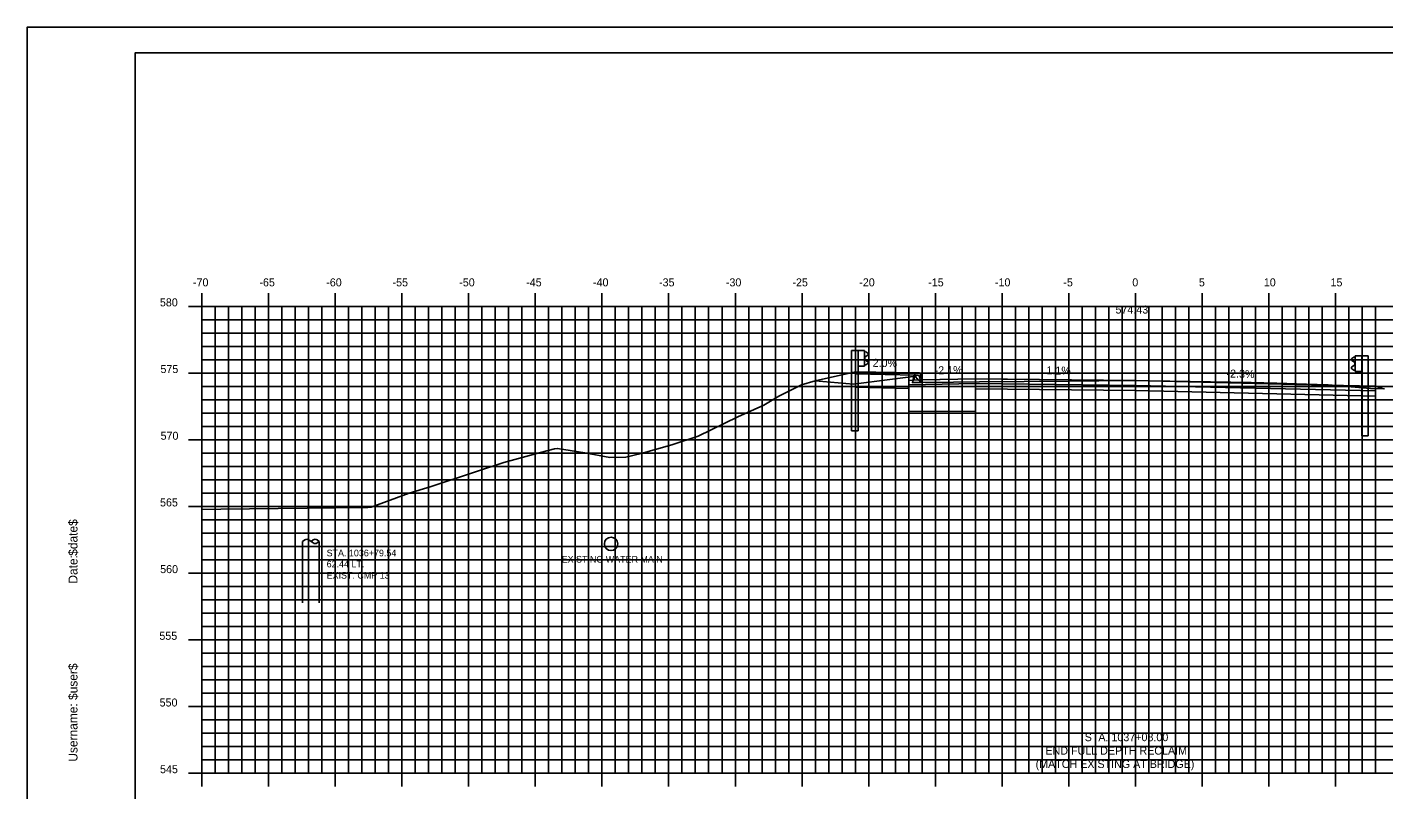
# Model space of a CAD drawing. Extents: x 1060559 to 1060729, y 779716 to 779826.
# Drawn here: x 1060559 to 1060660.7, y 779768.5 to 779825.6 of the extents above; entities that cross this region are included whole.
import ezdxf

# ---------------------------------------------------------------- set-up
doc = ezdxf.new("R2010")
doc.units = 0
for name, color, linetype in [('ANNOTATION', 7, 'Continuous'), ('BORDER', 7, 'Continuous'), ('D_Roadway_Berm', 7, 'Continuous'), ('D_Roadway_Centerline', 7, 'Continuous'), ('D_Roadway_Centerline_Text', 7, 'Continuous'), ('D_Roadway_Edge_Pavement', 7, 'Continuous'), ('D_Roadway_Edge_Shoulder', 7, 'Continuous'), ('D_Roadway_Pavement', 7, 'Continuous'), ('D_Roadway_Sidewalks_Paved', 7, 'Continuous'), ('D_Roadway_SubGrade', 7, 'Continuous'), ('D_Text_Monospaced', 7, 'Continuous'), ('Existing Water Main', 7, 'Continuous'), ('H_V ANNOTATION', 7, 'Continuous'), ('M_Guardrail', 7, 'Continuous'), ('MAJOR', 7, 'Continuous'), ('MINOR', 7, 'Continuous'), ('PLOT BOUNDARY', 7, 'Continuous'), ('S_Curb_Type_3', 7, 'Continuous'), ('S_Guardrail_Beam', 7, 'Continuous'), ('S_Roadway_Centerline', 7, 'Continuous'), ('S_Roadway_Edge_Pavement', 7, 'Continuous'), ('S_Utilities_Pole_Joint', 7, 'Continuous'), ('S_Utilities_Pole_Power', 7, 'Continuous')]:
    doc.layers.add(name, color=color, linetype=linetype)

msp = doc.modelspace()

# ---------------------------------------------------------------- linework, layer by layer
at = {"layer": 'ANNOTATION'}
msp.add_line((1060621.08, 779799.81), (1060618.06, 779799.13), dxfattribs=at)
at = {"layer": 'BORDER'}
msp.add_lwpolyline([(1060567.08, 779718.71), (1060727.08, 779718.71), (1060727.08, 779823.71), (1060567.08, 779823.71)], close=True, dxfattribs=at)
at = {"layer": 'D_Roadway_Berm'}
msp.add_lwpolyline([(1060626.08, 779799.19), (1060626.08, 779799.19)], dxfattribs=at)
at = {"layer": 'D_Roadway_Centerline'}
for points in [[(1060621.08, 779799.81), (1060625.66, 779799.72), (1060625.83, 779799.73), (1060625.89, 779799.72), (1060625.93, 779799.68), (1060625.96, 779799.63), (1060626.08, 779799.19)], [(1060625.82, 779799.17), (1060626.07, 779799.19), (1060626.08, 779799.19), (1060626.08, 779799.19), (1060630.08, 779799.27), (1060642.08, 779799.14), (1060654.08, 779798.86), (1060660.08, 779798.73), (1060660.66, 779798.53)]]:
    msp.add_lwpolyline(points, dxfattribs=at)
at = {"layer": 'D_Roadway_Edge_Pavement'}
msp.add_lwpolyline([(1060630.08, 779799.27), (1060630.08, 779799.27), (1060642.08, 779799.14), (1060654.08, 779798.86), (1060642.08, 779799.14), (1060642.08, 779799.14)], close=True, dxfattribs=at)
at = {"layer": 'D_Roadway_Edge_Shoulder'}
msp.add_line((1060654.08, 779798.86), (1060660.08, 779798.73), dxfattribs=at)
msp.add_lwpolyline([(1060625.46, 779799.17), (1060626.08, 779799.19), (1060630.08, 779799.27), (1060630.08, 779798.92), (1060625.08, 779798.82)], dxfattribs=at)
msp.add_lwpolyline([(1060630.08, 779799.27), (1060626.08, 779799.19), (1060630.08, 779799.27)], close=True, dxfattribs=at)
at = {"layer": 'D_Roadway_Pavement'}
for p, q in [((1060626.08, 779799.19), (1060630.08, 779799.27)), ((1060630.08, 779799.27), (1060630.08, 779796.86))]:
    msp.add_line(p, q, dxfattribs=at)
msp.add_lwpolyline([(1060630.08, 779796.86), (1060625.08, 779796.84), (1060625.08, 779798.82)], dxfattribs=at)
msp.add_lwpolyline([(1060630.08, 779799.27), (1060630.08, 779799.27), (1060642.08, 779799.14), (1060642.08, 779799.14)], close=True, dxfattribs=at)
at = {"layer": 'D_Roadway_Sidewalks_Paved'}
msp.add_lwpolyline([(1060625.66, 779799.72), (1060621.08, 779799.81), (1060621.08, 779799.64), (1060625.53, 779799.55), (1060625.54, 779799.62), (1060625.56, 779799.67), (1060625.6, 779799.7)], close=True, dxfattribs=at)
msp.add_lwpolyline([(1060626.07, 779799.19), (1060626.08, 779799.19), (1060626.08, 779799.19), (1060626.07, 779799.02), (1060626.07, 779799.02), (1060626.07, 779799.19)], dxfattribs=at)
at = {"layer": 'D_Roadway_SubGrade'}
for points in [[(1060625.53, 779799.55), (1060621.08, 779799.64), (1060621.08, 779798.64), (1060625.07, 779798.56), (1060625.08, 779798.82), (1060625.08, 779799.15), (1060625.46, 779799.17)], [(1060630.08, 779799.27), (1060630.08, 779799.27), (1060626.1, 779799.19), (1060626.07, 779799.19), (1060626.07, 779799.19), (1060626.08, 779799.19), (1060626.08, 779799.19), (1060630.08, 779799.27), (1060634.08, 779799.23), (1060634.08, 779799.23)]]:
    msp.add_lwpolyline(points, close=True, dxfattribs=at)
for points in [[(1060626.07, 779799.02), (1060626.08, 779799.19), (1060626.08, 779799.19), (1060626.07, 779799.19), (1060626.07, 779799.02), (1060626.07, 779799.02)], [(1060630.08, 779799.27), (1060630.08, 779798.92), (1060642.08, 779798.78), (1060660.08, 779798.37)], [(1060630.08, 779799.27), (1060630.08, 779798.52), (1060642.08, 779798.39), (1060660.08, 779797.98), (1060660.08, 779798.73)]]:
    msp.add_lwpolyline(points, dxfattribs=at)
at = {"layer": 'Existing Water Main'}
msp.add_circle((1060602.76, 779786.9), 0.501, dxfattribs=at)
at = {"layer": 'M_Guardrail'}
for p, q in [((1060620.79, 779801.39), (1060620.79, 779795.39)), ((1060621.28, 779801.39), (1060620.79, 779801.39)), ((1060659.04, 779801), (1060659.53, 779801)), ((1060659.53, 779801), (1060659.53, 779795)), ((1060621.28, 779795.39), (1060621.28, 779800.22)), ((1060659.04, 779795), (1060659.04, 779799.83)), ((1060621.28, 779795.39), (1060620.79, 779795.39)), ((1060659.04, 779795), (1060659.53, 779795))]:
    msp.add_line(p, q, dxfattribs=at)
at = {"layer": 'MAJOR'}
for p, q in [((1060572.08, 779805.71), (1060572.08, 779804.71)), ((1060577.08, 779805.71), (1060577.08, 779804.71)), ((1060582.08, 779805.71), (1060582.08, 779804.71)), ((1060587.08, 779805.71), (1060587.08, 779804.71)), ((1060592.08, 779805.71), (1060592.08, 779804.71)), ((1060597.08, 779805.71), (1060597.08, 779804.71)), ((1060602.08, 779805.71), (1060602.08, 779804.71)), ((1060607.08, 779805.71), (1060607.08, 779804.71)), ((1060612.08, 779805.71), (1060612.08, 779804.71)), ((1060617.08, 779805.71), (1060617.08, 779804.71)), ((1060622.08, 779805.71), (1060622.08, 779804.71)), ((1060627.08, 779805.71), (1060627.08, 779804.71)), ((1060632.08, 779805.71), (1060632.08, 779804.71)), ((1060637.08, 779805.71), (1060637.08, 779804.71)), ((1060642.08, 779805.71), (1060642.08, 779804.71)), ((1060647.08, 779805.71), (1060647.08, 779804.71)), ((1060652.08, 779805.71), (1060652.08, 779804.71)), ((1060657.08, 779805.71), (1060657.08, 779804.71)), ((1060571.08, 779804.71), (1060572.08, 779804.71)), ((1060572.08, 779804.71), (1060712.08, 779804.71)), ((1060572.08, 779769.71), (1060572.08, 779804.71)), ((1060572.08, 779769.71), (1060572.08, 779804.71)), ((1060572.08, 779804.71), (1060712.08, 779804.71)), ((1060577.08, 779769.71), (1060577.08, 779804.71)), ((1060582.08, 779769.71), (1060582.08, 779804.71)), ((1060587.08, 779769.71), (1060587.08, 779804.71)), ((1060592.08, 779769.71), (1060592.08, 779804.71)), ((1060597.08, 779769.71), (1060597.08, 779804.71)), ((1060602.08, 779769.71), (1060602.08, 779804.71)), ((1060607.08, 779769.71), (1060607.08, 779804.71)), ((1060612.08, 779769.71), (1060612.08, 779804.71)), ((1060617.08, 779769.71), (1060617.08, 779804.71)), ((1060622.08, 779769.71), (1060622.08, 779804.71)), ((1060627.08, 779769.71), (1060627.08, 779804.71)), ((1060632.08, 779769.71), (1060632.08, 779804.71)), ((1060637.08, 779769.71), (1060637.08, 779804.71)), ((1060642.08, 779769.71), (1060642.08, 779804.71)), ((1060647.08, 779769.71), (1060647.08, 779804.71)), ((1060652.08, 779769.71), (1060652.08, 779804.71)), ((1060657.08, 779769.71), (1060657.08, 779804.71)), ((1060571.08, 779799.71), (1060572.08, 779799.71)), ((1060572.08, 779799.71), (1060712.08, 779799.71)), ((1060571.08, 779794.71), (1060572.08, 779794.71)), ((1060572.08, 779794.71), (1060712.08, 779794.71)), ((1060571.08, 779789.71), (1060572.08, 779789.71)), ((1060572.08, 779789.71), (1060712.08, 779789.71)), ((1060571.08, 779784.71), (1060572.08, 779784.71)), ((1060572.08, 779784.71), (1060712.08, 779784.71)), ((1060571.08, 779779.71), (1060572.08, 779779.71)), ((1060572.08, 779779.71), (1060712.08, 779779.71)), ((1060571.08, 779774.71), (1060572.08, 779774.71)), ((1060572.08, 779774.71), (1060712.08, 779774.71)), ((1060571.08, 779769.71), (1060572.08, 779769.71)), ((1060572.08, 779769.71), (1060712.08, 779769.71)), ((1060572.08, 779769.71), (1060712.08, 779769.71)), ((1060572.08, 779768.7), (1060572.08, 779769.71)), ((1060577.08, 779768.7), (1060577.08, 779769.71)), ((1060582.08, 779768.7), (1060582.08, 779769.71)), ((1060587.08, 779768.7), (1060587.08, 779769.71)), ((1060592.08, 779768.7), (1060592.08, 779769.71)), ((1060597.08, 779768.7), (1060597.08, 779769.71)), ((1060602.08, 779768.7), (1060602.08, 779769.71)), ((1060607.08, 779768.7), (1060607.08, 779769.71)), ((1060612.08, 779768.7), (1060612.08, 779769.71)), ((1060617.08, 779768.7), (1060617.08, 779769.71)), ((1060622.08, 779768.7), (1060622.08, 779769.71)), ((1060627.08, 779768.7), (1060627.08, 779769.71)), ((1060632.08, 779768.7), (1060632.08, 779769.71)), ((1060637.08, 779768.7), (1060637.08, 779769.71)), ((1060642.08, 779768.7), (1060642.08, 779769.71)), ((1060647.08, 779768.7), (1060647.08, 779769.71)), ((1060652.08, 779768.7), (1060652.08, 779769.71)), ((1060657.08, 779768.7), (1060657.08, 779769.71))]:
    msp.add_line(p, q, dxfattribs=at)
at = {"layer": 'MINOR'}
for p, q in [((1060573.08, 779769.71), (1060573.08, 779804.71)), ((1060574.08, 779769.71), (1060574.08, 779804.71)), ((1060575.08, 779769.71), (1060575.08, 779804.71)), ((1060576.08, 779769.71), (1060576.08, 779804.71)), ((1060578.08, 779769.71), (1060578.08, 779804.71)), ((1060579.08, 779769.71), (1060579.08, 779804.71)), ((1060580.08, 779769.71), (1060580.08, 779804.71)), ((1060581.08, 779769.71), (1060581.08, 779804.71)), ((1060583.08, 779769.71), (1060583.08, 779804.71)), ((1060584.08, 779769.71), (1060584.08, 779804.71)), ((1060585.08, 779769.71), (1060585.08, 779804.71)), ((1060586.08, 779769.71), (1060586.08, 779804.71)), ((1060588.08, 779769.71), (1060588.08, 779804.71)), ((1060589.08, 779769.71), (1060589.08, 779804.71)), ((1060590.08, 779769.71), (1060590.08, 779804.71)), ((1060591.08, 779769.71), (1060591.08, 779804.71)), ((1060593.08, 779769.71), (1060593.08, 779804.71)), ((1060594.08, 779769.71), (1060594.08, 779804.71)), ((1060595.08, 779769.71), (1060595.08, 779804.71)), ((1060596.08, 779769.71), (1060596.08, 779804.71)), ((1060598.08, 779769.71), (1060598.08, 779804.71)), ((1060599.08, 779769.71), (1060599.08, 779804.71)), ((1060600.08, 779769.71), (1060600.08, 779804.71)), ((1060601.08, 779769.71), (1060601.08, 779804.71)), ((1060603.08, 779769.71), (1060603.08, 779804.71)), ((1060604.08, 779769.71), (1060604.08, 779804.71)), ((1060605.08, 779769.71), (1060605.08, 779804.71)), ((1060606.08, 779769.71), (1060606.08, 779804.71)), ((1060608.08, 779769.71), (1060608.08, 779804.71)), ((1060609.08, 779769.71), (1060609.08, 779804.71)), ((1060610.08, 779769.71), (1060610.08, 779804.71)), ((1060611.08, 779769.71), (1060611.08, 779804.71)), ((1060613.08, 779769.71), (1060613.08, 779804.71)), ((1060614.08, 779769.71), (1060614.08, 779804.71)), ((1060615.08, 779769.71), (1060615.08, 779804.71)), ((1060616.08, 779769.71), (1060616.08, 779804.71)), ((1060618.08, 779769.71), (1060618.08, 779804.71)), ((1060619.08, 779769.71), (1060619.08, 779804.71)), ((1060620.08, 779769.71), (1060620.08, 779804.71)), ((1060621.08, 779769.71), (1060621.08, 779804.71)), ((1060623.08, 779769.71), (1060623.08, 779804.71)), ((1060624.08, 779769.71), (1060624.08, 779804.71)), ((1060625.08, 779769.71), (1060625.08, 779804.71)), ((1060626.08, 779769.71), (1060626.08, 779804.71)), ((1060628.08, 779769.71), (1060628.08, 779804.71)), ((1060629.08, 779769.71), (1060629.08, 779804.71)), ((1060630.08, 779769.71), (1060630.08, 779804.71)), ((1060631.08, 779769.71), (1060631.08, 779804.71)), ((1060633.08, 779769.71), (1060633.08, 779804.71)), ((1060634.08, 779769.71), (1060634.08, 779804.71)), ((1060635.08, 779769.71), (1060635.08, 779804.71)), ((1060636.08, 779769.71), (1060636.08, 779804.71)), ((1060638.08, 779769.71), (1060638.08, 779804.71)), ((1060639.08, 779769.71), (1060639.08, 779804.71)), ((1060640.08, 779769.71), (1060640.08, 779804.71)), ((1060641.08, 779769.71), (1060641.08, 779804.71)), ((1060643.08, 779769.71), (1060643.08, 779804.71)), ((1060644.08, 779769.71), (1060644.08, 779804.71)), ((1060645.08, 779769.71), (1060645.08, 779804.71)), ((1060646.08, 779769.71), (1060646.08, 779804.71)), ((1060648.08, 779769.71), (1060648.08, 779804.71)), ((1060649.08, 779769.71), (1060649.08, 779804.71)), ((1060650.08, 779769.71), (1060650.08, 779804.71)), ((1060651.08, 779769.71), (1060651.08, 779804.71)), ((1060653.08, 779769.71), (1060653.08, 779804.71)), ((1060654.08, 779769.71), (1060654.08, 779804.71)), ((1060655.08, 779769.71), (1060655.08, 779804.71)), ((1060656.08, 779769.71), (1060656.08, 779804.71)), ((1060658.08, 779769.71), (1060658.08, 779804.71)), ((1060659.08, 779769.71), (1060659.08, 779804.71)), ((1060660.08, 779769.71), (1060660.08, 779804.71)), ((1060572.08, 779803.71), (1060712.08, 779803.71)), ((1060572.08, 779803.71), (1060573.08, 779803.71)), ((1060572.08, 779802.71), (1060712.08, 779802.71)), ((1060572.08, 779802.71), (1060573.08, 779802.71)), ((1060572.08, 779801.71), (1060712.08, 779801.71)), ((1060572.08, 779801.71), (1060573.08, 779801.71)), ((1060572.08, 779800.71), (1060712.08, 779800.71)), ((1060572.08, 779800.71), (1060573.08, 779800.71)), ((1060572.08, 779798.71), (1060712.08, 779798.71)), ((1060572.08, 779798.71), (1060573.08, 779798.71)), ((1060572.08, 779797.71), (1060712.08, 779797.71)), ((1060572.08, 779797.71), (1060573.08, 779797.71)), ((1060572.08, 779796.71), (1060712.08, 779796.71)), ((1060572.08, 779796.71), (1060573.08, 779796.71)), ((1060572.08, 779795.71), (1060712.08, 779795.71)), ((1060572.08, 779795.71), (1060573.08, 779795.71)), ((1060572.08, 779793.71), (1060712.08, 779793.71)), ((1060572.08, 779793.71), (1060573.08, 779793.71)), ((1060572.08, 779792.71), (1060712.08, 779792.71)), ((1060572.08, 779792.71), (1060573.08, 779792.71)), ((1060572.08, 779791.71), (1060712.08, 779791.71)), ((1060572.08, 779791.71), (1060573.08, 779791.71)), ((1060572.08, 779790.71), (1060712.08, 779790.71)), ((1060572.08, 779790.71), (1060573.08, 779790.71)), ((1060572.08, 779788.71), (1060712.08, 779788.71)), ((1060572.08, 779788.71), (1060573.08, 779788.71)), ((1060572.08, 779787.71), (1060712.08, 779787.71)), ((1060572.08, 779787.71), (1060573.08, 779787.71)), ((1060572.08, 779786.71), (1060712.08, 779786.71)), ((1060572.08, 779786.71), (1060573.08, 779786.71)), ((1060572.08, 779785.71), (1060712.08, 779785.71)), ((1060572.08, 779785.71), (1060573.08, 779785.71)), ((1060572.08, 779783.71), (1060712.08, 779783.71)), ((1060572.08, 779783.71), (1060573.08, 779783.71)), ((1060572.08, 779782.71), (1060712.08, 779782.71)), ((1060572.08, 779782.71), (1060573.08, 779782.71)), ((1060572.08, 779781.71), (1060712.08, 779781.71)), ((1060572.08, 779781.71), (1060573.08, 779781.71)), ((1060572.08, 779780.71), (1060712.08, 779780.71)), ((1060572.08, 779780.71), (1060573.08, 779780.71)), ((1060572.08, 779778.71), (1060712.08, 779778.71)), ((1060572.08, 779778.71), (1060573.08, 779778.71)), ((1060572.08, 779777.71), (1060712.08, 779777.71)), ((1060572.08, 779777.71), (1060573.08, 779777.71)), ((1060572.08, 779776.71), (1060712.08, 779776.71)), ((1060572.08, 779776.71), (1060573.08, 779776.71)), ((1060572.08, 779775.71), (1060712.08, 779775.71)), ((1060572.08, 779775.71), (1060573.08, 779775.71)), ((1060572.08, 779773.71), (1060712.08, 779773.71)), ((1060572.08, 779773.71), (1060573.08, 779773.71)), ((1060572.08, 779772.71), (1060712.08, 779772.71)), ((1060572.08, 779772.71), (1060573.08, 779772.71)), ((1060572.08, 779771.71), (1060712.08, 779771.71)), ((1060572.08, 779771.71), (1060573.08, 779771.71)), ((1060572.08, 779770.71), (1060712.08, 779770.71)), ((1060572.08, 779770.71), (1060573.08, 779770.71))]:
    msp.add_line(p, q, dxfattribs=at)
at = {"layer": 'PLOT BOUNDARY'}
msp.add_lwpolyline([(1060558.99, 779715.65), (1060728.99, 779715.65), (1060728.99, 779825.65), (1060558.99, 779825.65)], close=True, dxfattribs=at)
at = {"layer": 'S_Curb_Type_3'}
for points in [[(1060625.88, 779799.44), (1060625.98, 779799), (1060625.36, 779799), (1060625.46, 779799.44)], [(1060625.58, 779799.54), (1060625.76, 779799.54)]]:
    msp.add_lwpolyline(points, dxfattribs=at)
for centre, start, end in [((1060625.58, 779799.42), 90, 167.0054), ((1060625.76, 779799.42), 12.9946, 90)]:
    msp.add_arc(centre, 0.125, start, end, dxfattribs=at)
at = {"layer": 'S_Guardrail_Beam'}
for p, q in [((1060621.77, 779801.39), (1060621.28, 779801.39)), ((1060621.28, 779801.39), (1060621.28, 779800.22)), ((1060621.77, 779800.22), (1060621.77, 779801.39)), ((1060621.77, 779801.32), (1060621.85, 779801.3)), ((1060621.78, 779800.85), (1060621.78, 779800.76)), ((1060622.01, 779801.05), (1060621.82, 779800.92)), ((1060621.82, 779800.7), (1060622.01, 779800.56)), ((1060621.87, 779801.3), (1060622.01, 779801.2)), ((1060658.45, 779800.9), (1060658.3, 779800.8)), ((1060658.3, 779800.66), (1060658.5, 779800.52)), ((1060658.55, 779800.93), (1060658.46, 779800.91)), ((1060658.55, 779801), (1060659.04, 779801)), ((1060658.55, 779799.83), (1060658.55, 779801)), ((1060659.04, 779801), (1060659.04, 779799.83)), ((1060621.28, 779800.22), (1060621.77, 779800.22)), ((1060621.85, 779800.31), (1060621.77, 779800.3)), ((1060622.01, 779800.42), (1060621.87, 779800.32)), ((1060658.5, 779800.31), (1060658.3, 779800.17)), ((1060658.3, 779800.03), (1060658.45, 779799.93)), ((1060658.46, 779799.92), (1060658.55, 779799.9)), ((1060658.53, 779800.46), (1060658.53, 779800.37)), ((1060659.04, 779799.83), (1060658.55, 779799.83))]:
    msp.add_line(p, q, dxfattribs=at)
for centre, major_axis, start_param, end_param in [((1060621.86, 779800.85), (-0.0789, 0), 5.323254, 6.283185), ((1060621.86, 779800.76), (-0.0789, 0), 6.283185, 7.243116), ((1060621.85, 779801.26), (0.0417, 0), 0.959931, 1.396263), ((1060621.96, 779801.13), (0.0877, 0), 5.323254, 7.243116), ((1060658.35, 779800.73), (-0.0877, 0), 5.323254, 7.243116), ((1060658.47, 779800.87), (-0.0417, 0), 4.886922, 5.323254), ((1060621.85, 779800.35), (0.0417, 0), 4.886922, 5.323254), ((1060621.96, 779800.49), (0.0877, 0), 5.323254, 7.243116), ((1060658.35, 779800.1), (-0.0877, 0), 5.323254, 7.243116), ((1060658.47, 779799.96), (-0.0417, 0), 0.959931, 1.396263), ((1060658.45, 779800.46), (0.0789, 0), 0, 0.959931), ((1060658.45, 779800.37), (0.0789, 0), 5.323254, 6.283185)]:
    msp.add_ellipse(centre, major_axis=major_axis, ratio=0.995501, start_param=start_param, end_param=end_param, dxfattribs=at)
at = {"layer": 'S_Roadway_Centerline'}
for points in [[(1060572.08, 779789.48), (1060573.52, 779789.51), (1060584.29, 779789.63), (1060584.54, 779789.63), (1060584.78, 779789.65), (1060587.63, 779790.7), (1060589.19, 779791.18), (1060592.61, 779792.3), (1060594.73, 779793), (1060597.48, 779793.75), (1060598.51, 779794.02), (1060598.74, 779794.06), (1060600.79, 779793.74), (1060602.68, 779793.39), (1060603.88, 779793.41), (1060605.02, 779793.68), (1060607.33, 779794.34), (1060609.29, 779794.97), (1060612.27, 779796.44), (1060614.21, 779797.31), (1060615.33, 779797.99), (1060617.03, 779798.83), (1060618.06, 779799.13), (1060620.95, 779798.88), (1060623.65, 779799.22), (1060625.61, 779799.48), (1060625.64, 779799.36), (1060625.76, 779799.24), (1060625.98, 779799), (1060628.43, 779799.02), (1060630.38, 779799.06), (1060637.09, 779799.1), (1060641.6, 779799.14), (1060650.75, 779798.99), (1060652.67, 779798.96), (1060654.9, 779798.87), (1060656.53, 779798.83), (1060659.7, 779798.56), (1060660.74, 779798.53)], [(1060641.6, 779799.14), (1060641.6, 779799.14)]]:
    msp.add_lwpolyline(points, dxfattribs=at)
at = {"layer": 'S_Roadway_Edge_Pavement'}
msp.add_lwpolyline([(1060625.98, 779799), (1060625.98, 779799)], dxfattribs=at)
at = {"layer": 'S_Utilities_Pole_Joint'}
for p, q in [((1060579.64, 779787.09), (1060579.8, 779787.2)), ((1060580.11, 779787.2), (1060580.27, 779787.09)), ((1060580.42, 779787.2), (1060580.27, 779787.09)), ((1060580.27, 779787.09), (1060580.42, 779786.98)), ((1060580.89, 779787.09), (1060580.74, 779787.2)), ((1060580.74, 779786.98), (1060580.89, 779787.09))]:
    msp.add_line(p, q, dxfattribs=at)
for centre, start, end in [((1060579.96, 779786.98), 90, 125.2644), ((1060579.96, 779786.98), 54.7356, 90), ((1060580.58, 779786.98), 90, 125.2644), ((1060580.58, 779787.2), 234.7356, 270), ((1060580.58, 779786.98), 54.7356, 90), ((1060580.58, 779787.2), 270, 305.2644)]:
    msp.add_arc(centre, 0.271, start, end, dxfattribs=at)
at = {"layer": 'S_Utilities_Pole_Power'}
for p, q in [((1060579.64, 779782.47), (1060579.64, 779787.09)), ((1060580.89, 779782.47), (1060580.89, 779787.09))]:
    msp.add_line(p, q, dxfattribs=at)

# ---------------------------------------------------------------- texts
at = {"layer": 'ANNOTATION'}
for s, rotation, p in [('2.0%', 358.8542, (1060622.37, 779800.18)), ('-2.1%', 1.2249, (1060627.03, 779799.61)), ('1.1%', 359.342, (1060635.4, 779799.61)), ('-2.3%', 358.7015, (1060648.9, 779799.38))]:
    msp.add_text(s, height=0.6, rotation=rotation, dxfattribs=at).set_placement(p)
for s, p in [('STA. 1037+08.00', (1060638.27, 779772.11)), ('END FULL DEPTH RECLAIM', (1060635.33, 779771.1)), ('(MATCH EXISTING AT BRIDGE)', (1060634.59, 779770.1))]:
    msp.add_text(s, height=0.6, dxfattribs=at).set_placement(p)
at = {"layer": 'BORDER'}
for s, p in [('$date$', (1060562.76, 779786.01)), ('Date:', (1060562.76, 779783.92)), ('$user$', (1060562.76, 779775.2)), ('Username:', (1060562.76, 779770.57))]:
    msp.add_text(s, height=0.67, rotation=90, dxfattribs=at).set_placement(p)
at = {"layer": 'D_Roadway_Centerline_Text'}
msp.add_text('574.43', height=0.6, dxfattribs=at).set_placement((1060640.58, 779804.17))
at = {"layer": 'D_Text_Monospaced'}
for s, p in [('STA. 1036+79.54', (1060581.44, 779785.97)), ('62.44 LT.', (1060581.44, 779785.14)), ('EXISTING WATER MAIN', (1060599.06, 779785.5)), ('EXIST. CMP 13', (1060581.44, 779784.3))]:
    msp.add_text(s, height=0.5, dxfattribs=at).set_placement(p)
at = {"layer": 'H_V ANNOTATION'}
for s, p in [('-70', (1060571.42, 779806.21)), ('-65', (1060576.4, 779806.21)), ('-60', (1060581.41, 779806.21)), ('-55', (1060586.38, 779806.21)), ('-50', (1060591.38, 779806.21)), ('-45', (1060596.4, 779806.21)), ('-40', (1060601.41, 779806.21)), ('-35', (1060606.36, 779806.21)), ('-30', (1060611.37, 779806.21)), ('-25', (1060616.36, 779806.21)), ('-20', (1060621.37, 779806.21)), ('-15', (1060626.54, 779806.21)), ('-10', (1060631.54, 779806.21)), ('-5', (1060636.67, 779806.21)), ('0', (1060641.84, 779806.21)), ('5', (1060646.83, 779806.21)), ('10', (1060651.7, 779806.21)), ('15', (1060656.7, 779806.21)), ('580', (1060568.94, 779804.71)), ('575', (1060568.98, 779799.71)), ('570', (1060568.99, 779794.71)), ('565', (1060568.95, 779789.71)), ('560', (1060568.96, 779784.71)), ('555', (1060568.9, 779779.71)), ('550', (1060568.92, 779774.71)), ('545', (1060568.95, 779769.71))]:
    msp.add_text(s, height=0.6, dxfattribs=at).set_placement(p)
at = {"layer": 'MAJOR'}
msp.add_text('-', height=0.006, dxfattribs=at).set_placement((1060572.08, 779769.71))
at = {"layer": 'S_Roadway_Centerline'}
for s in ['C', 'L']:
    msp.add_text(s, height=0.0146, dxfattribs=at).set_placement((1060641.6, 779799.14))

doc.saveas('drawing.dxf')
